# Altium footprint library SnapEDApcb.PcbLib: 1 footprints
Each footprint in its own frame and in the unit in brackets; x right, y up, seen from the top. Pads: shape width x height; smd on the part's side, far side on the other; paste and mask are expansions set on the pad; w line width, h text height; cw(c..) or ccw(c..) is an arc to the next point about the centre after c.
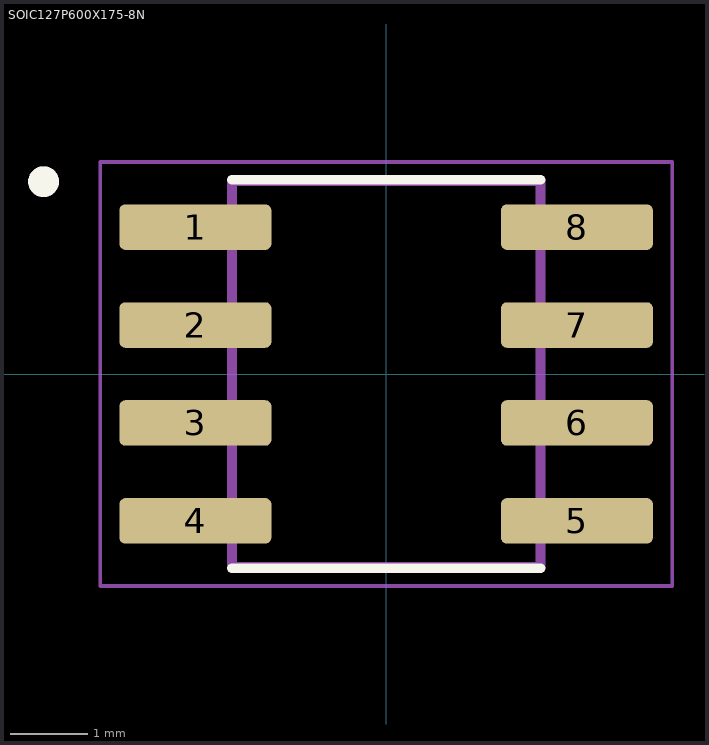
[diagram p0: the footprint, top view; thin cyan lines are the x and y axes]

## SOIC127P600X175-8N [mm]
pads (8):
  rrect25% 1.97x0.59 smd: 1(-2.475,1.905) 2(-2.475,0.635) 3(-2.475,-0.635) 4(-2.475,-1.905) 5(2.475,-1.905) 6(2.475,-0.635) 7(2.475,0.635) 8(2.475,1.905)
Top Overlay:
  circle w0.2: c-4.445,2.495 r0.1
  lines w0.127: -2,-2.52 2,-2.52 ; -2,2.52 2,2.52
Mechanical 13:
  circle w0.2: c-4.445,2.495 r0.1
  lines w0.127: -2,-2.5 2,-2.5 2,2.5 -2,2.5 -2,-2.5
Mechanical 15:
  lines w0.05: -3.71,-2.75 3.71,-2.75 3.71,2.75 -3.71,2.75 -3.71,-2.75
